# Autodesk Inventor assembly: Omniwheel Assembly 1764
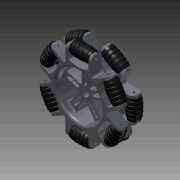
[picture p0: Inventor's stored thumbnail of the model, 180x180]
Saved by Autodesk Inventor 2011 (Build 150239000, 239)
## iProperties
Created: 2007-11
Part Number: Omniwheel Assembly 1764
Document SubType Name: Assembly
Designer: lwoods
Mass: 807.037 g
Surface Area: 1296.28 cm^2
Volume: 334.333 cm^3
Density: 2.41387 g/cm^3
Author: lwoods
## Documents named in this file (4)
- R:\CAD Archives\Wheels\Omniwheel 1764\Omniwheel Assembly 1764.iam
- R:\CAD Archives\Wheels\Omniwheel 1764\Roller Axle V4 1764.ipt
- R:\CAD Archives\Wheels\Omniwheel 1764\Omnidrive 1764.ipt
- R:\CAD Archives\Wheels\Omniwheel 1764\Roller Asssembly 1764.iam
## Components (25 placed, 3 different names)
1. Omnidrive 1764:1 — Insert:1, Insert:2, Insert:3, Insert:4, Insert:5, Insert:6, Insert:7, Insert:8, Insert:9, Insert:10, Insert:11, Insert:12, Insert:16, Insert:17, Insert:19, Insert:20
2. Roller Axle V4 1764:1 — Insert:11, Insert:24
3. Roller Axle V4 1764:2 — Insert:8
4. Roller Axle V4 1764:3 — Insert:12, Insert:23
5. Roller Axle V4 1764:4 — Insert:10, Insert:22
6. Roller Axle V4 1764:5 — Insert:3, Insert:14
7. Roller Axle V4 1764:6 — Insert:4, Insert:18
8. Roller Axle V4 1764:7 — Insert:6
9. Roller Axle V4 1764:8 — Insert:2
10. Roller Axle V4 1764:9 — Insert:1, Insert:13
11. Roller Axle V4 1764:10 — Insert:5
12. Roller Axle V4 1764:11 — Insert:9, Insert:15
13. Roller Axle V4 1764:12 — Insert:7, Insert:21
14. Roller Asssembly 1764:1 [sub-assembly] — Insert:18
15. Roller Asssembly 1764:2 [sub-assembly] — Insert:20
16. Roller Asssembly 1764:3 [sub-assembly] — Insert:17
17. Roller Asssembly 1764:4 [sub-assembly] — Insert:19
18. Roller Asssembly 1764:5 [sub-assembly] — Insert:21
19. Roller Asssembly 1764:6 [sub-assembly] — Insert:22
20. Roller Asssembly 1764:7 [sub-assembly] — Insert:23
21. Roller Asssembly 1764:8 [sub-assembly] — Insert:24
22. Roller Asssembly 1764:9 [sub-assembly] — Insert:16
23. Roller Asssembly 1764:10 [sub-assembly] — Insert:15
24. Roller Asssembly 1764:11 [sub-assembly] — Insert:13
25. Roller Asssembly 1764:12 [sub-assembly] — Insert:14
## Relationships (24: Insert 24)
- Insert:1: Omnidrive 1764:1 ↔ Roller Axle V4 1764:9
- Insert:2: Omnidrive 1764:1 ↔ Roller Axle V4 1764:8
- Insert:3: Omnidrive 1764:1 ↔ Roller Axle V4 1764:5
- Insert:4: Omnidrive 1764:1 ↔ Roller Axle V4 1764:6
- Insert:5: Omnidrive 1764:1 ↔ Roller Axle V4 1764:10
- Insert:6: Omnidrive 1764:1 ↔ Roller Axle V4 1764:7
- Insert:7: Omnidrive 1764:1 ↔ Roller Axle V4 1764:12
- Insert:8: Omnidrive 1764:1 ↔ Roller Axle V4 1764:2
- Insert:9: Omnidrive 1764:1 ↔ Roller Axle V4 1764:11
- Insert:10: Omnidrive 1764:1 ↔ Roller Axle V4 1764:4
- Insert:11: Omnidrive 1764:1 ↔ Roller Axle V4 1764:1
- Insert:12: Omnidrive 1764:1 ↔ Roller Axle V4 1764:3
- Insert:13: Roller Axle V4 1764:9 ↔ Roller Asssembly 1764:11
- Insert:14: Roller Axle V4 1764:5 ↔ Roller Asssembly 1764:12
- Insert:15: Roller Axle V4 1764:11 ↔ Roller Asssembly 1764:10
- Insert:16: Omnidrive 1764:1 ↔ Roller Asssembly 1764:9
- Insert:17: Omnidrive 1764:1 ↔ Roller Asssembly 1764:3
- Insert:18: Roller Axle V4 1764:6 ↔ Roller Asssembly 1764:1
- Insert:19: Omnidrive 1764:1 ↔ Roller Asssembly 1764:4
- Insert:20: Omnidrive 1764:1 ↔ Roller Asssembly 1764:2
- Insert:21: Roller Axle V4 1764:12 ↔ Roller Asssembly 1764:5
- Insert:22: Roller Axle V4 1764:4 ↔ Roller Asssembly 1764:6
- Insert:23: Roller Axle V4 1764:3 ↔ Roller Asssembly 1764:7
- Insert:24: Roller Axle V4 1764:1 ↔ Roller Asssembly 1764:8
